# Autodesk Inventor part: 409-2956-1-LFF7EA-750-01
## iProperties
Created: 2010-06
Part Number: 409-2956-1-LFF7EA-750-01
Material: Sch40 CS PIPE SEAMLESS
Description: PIPE
Document SubType Name: Modeling
Designer: S. Boerckel
Engineer: Steve Boerckel
Mass: 4907.03 g
Surface Area: 3209.99 cm^2
Volume: 625.099 cm^3
Density: 7.85 g/cm^3
Cost Center: 4"
SMR: =<COST CENTER> - <Material>
Length: 35.500 in
Title: 2"
Author: S. Boerckel
Revision Number: B
Subject: DEMIN WATER FORWARDING PUMP SKID-7EA
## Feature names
1. Extrusion1
